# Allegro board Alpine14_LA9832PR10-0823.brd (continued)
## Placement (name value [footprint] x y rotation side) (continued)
CU16  0.1U_0402_10V7K~D  [C_0402]  93.62 53.65 0 bottom
CU17  0.1U_0402_10V7K~D  [C_0402]  93.62 54.54 0 bottom
CU18  0.1U_0402_10V7K~D  [C_0402]  93.62 51.81 0 bottom
CU19  0.1U_0402_10V7K~D  [C_0402]  93.62 52.7 0 bottom
CU20  0.1U_0402_10V7K~D  [C_0402]  97.81 55.99 0 bottom
CU21  0.1U_0402_10V7K~D  [C_0402]  97.81 56.87 0 bottom
CU22  0.1U_0402_10V7K~D  [C_0402]  95.59 54.92 0 bottom
CU23  0.1U_0402_10V7K~D  [C_0402]  95.59 55.81 0 bottom
CV86  10U_0603_6.3V6M  [C_0603]  51.79 74.86 180 top
CV87  0.1U_0402_10V7K~D  [C_0402]  76.38 77.48 180 top
CV88  1U_0402_6.3V6K  [C_0402]  63.34 78.87 270 top
CV89  1U_0402_6.3V6K  [C_0402]  59.99 78.86 180 top
CV90  10U_0603_6.3V6M  [C_0603]  64.3 79.24 0 top
CV91  10U_0603_6.3V6M  [C_0603]  56.74 76.53 0 top
CV94  1U_0402_6.3V6K  [C_0402]  57.45 78.99 180 top
CV95  1U_0402_6.3V6K  [C_0402]  54.38 77.27 0 top
CV96  10U_0603_6.3V6M  [C_0603]  59.53 76.83 0 top
CV97  1U_0402_6.3V6K  [C_0402]  60.93 78.87 270 top
CV100  1U_0402_6.3V6K  [C_0402]  56.16 82.6 0 top
CV101  1U_0402_6.3V6K  [C_0402]  56.57 87.49 180 top
CV102  10U_0603_6.3V6M  [C_0603]  50.64 88.19 0 top
CV103  1U_0402_6.3V6K  [C_0402]  63.1 89.84 180 top
CV104  15P_0402_50V8J  [C_0402]  66.83 98.54 0 bottom
CV105  15P_0402_50V8J  [C_0402]  65.9 98.54 180 bottom
CV226  0.1U_0402_10V7K~D  [C_0402]  68.05 78.3 270 top
CV227  0.1U_0402_10V7K~D  [C_0402]  62.33 78.87 270 top
CV228  0.1U_0402_10V7K~D  [C_0402]  56.16 84.19 0 top
CV231  0.1U_0402_10V7K~D  [C_0402]  57.74 89.84 0 top
CV232  0.1U_0402_10V7K~D  [C_0402]  51.67 94.1 180 top
CV233  0.1U_0402_10V7K~D  [C_0402]  65.31 89.28 270 top
CV234  0.1U_0402_10V7K~D  [C_0402]  66.46 89.28 270 top
CV235  0.1U_0402_10V7K~D  [C_0402]  63.98 89.28 270 top
CV236  0.1U_0402_10V7K~D  [C_0402]  68.36 87.35 90 top
CV239  0.1U_0402_10V7K~D  [C_0402]  68.36 85.03 270 top
CV240  0.1U_0402_10V7K~D  [C_0402]  69.25 85.45 90 top
CV2401  0.1U_0402_10V7K~D  [C_0402]  77.58 68.19 180 top
CV2402  0.1U_0402_10V7K~D  [C_0402]  75.74 72.57 180 top
CV2403  0.1U_0402_10V7K~D  [C_0402]  75.74 71.62 180 top
CV2404  0.1U_0402_10V7K~D  [C_0402]  73.65 71.24 180 top
CV2405  0.1U_0402_10V7K~D  [C_0402]  73.65 70.35 180 top
CV2406  0.1U_0402_10V7K~D  [C_0402]  70.92 69.46 180 top
CV2407  0.1U_0402_10V7K~D  [C_0402]  70.91 70.35 180 top
CV2408  0.1U_0402_10V7K~D  [C_0402]  77.58 67.3 180 top
CV2901  0.01U_0402_16V7K~D  [C_0402]  35.42 100.45 180 bottom
CV2902  0.01U_0402_16V7K~D  [C_0402]  33.55 97.78 0 top
CV2918  10U_0603_6.3V6M~D  [C_0603]  41.12 97.97 0 top
CV2919  10U_0603_6.3V6M~D  [C_0603]  41.25 97.97 180 bottom
CV2920  10U_0603_6.3V6M~D  [C_0603]  41.18 69.71 0 bottom
CV2921  10U_0603_6.3V6M~D  [C_0603]  26.77 80.06 90 top
CV2926  1U_0402_6.3V6K~D  [C_0402]  27.16 88.89 180 top
CV2927  1U_0402_6.3V6K~D  [C_0402]  38.21 98.73 180 top
CV2928  1U_0402_6.3V6K~D  [C_0402]  38.95 68.95 0 bottom
CV2929  1U_0402_6.3V6K~D  [C_0402]  30.72 85.65 180 top
CV2930  1U_0402_6.3V6K~D  [C_0402]  30.91 97.78 180 top
CV2931  1U_0402_6.3V6K~D  [C_0402]  40.15 85.72 0 top
CV2932  1U_0402_6.3V6K~D  [C_0402]  31.77 97.78 0 top
CV2933  1U_0402_6.3V6K~D  [C_0402]  40.18 97.78 180 top
CV2934  0.1U_0402_10V7K~D  [C_0402]  40.15 84.76 0 top
CV2935  0.1U_0402_10V7K~D  [C_0402]  38.21 97.78 180 top
CV2936  0.1U_0402_10V7K~D  [C_0402]  31.65 85.65 0 top
CV2937  0.1U_0402_10V7K~D  [C_0402]  38.91 85.59 180 top
CV2938  0.1U_0402_10V7K~D  [C_0402]  40.18 98.73 180 top
CV2939  0.1U_0402_10V7K~D  [C_0402]  38.91 84.64 180 top
CV2940  0.1U_0402_10V7K~D  [C_0402]  38.72 97.78 180 bottom
CV2941  0.01U_0402_16V7K~D  [C_0402]  35.33 97.78 0 top
CV2942  0.01U_0402_16V7K~D  [C_0402]  32.92 69.84 0 top
CV2943  0.01U_0402_16V7K~D  [C_0402]  35.14 82.22 0 top
CV2944  0.01U_0402_16V7K~D  [C_0402]  38.2 68.11 90 top
CV2945  0.1U_0402_10V7K~D  [C_0402]  30.02 97.78 180 bottom
CV2946  0.1U_0402_10V7K~D  [C_0402]  30.88 97.78 0 bottom
CV2947  0.1U_0402_10V7K~D  [C_0402]  30.02 98.67 180 bottom
CV2948  0.1U_0402_10V7K~D  [C_0402]  30.88 98.67 0 bottom
CV2949  0.1U_0402_10V7K~D  [C_0402]  30.91 98.67 180 top
CV2950  1U_0402_6.3V6K~D  [C_0402]  31.77 98.67 0 top
CV2951  1U_0402_6.3V6K~D  [C_0402]  32.03 68.89 0 bottom
CV2952  1U_0402_6.3V6K~D  [C_0402]  29.32 69.84 180 bottom
CV2953  0.1U_0402_10V7K~D  [C_0402]  37.32 68.95 180 bottom
CV2954  0.1U_0402_10V7K~D  [C_0402]  29.32 68.89 180 bottom
CV2955  0.1U_0402_10V7K~D  [C_0402]  32.03 69.84 0 bottom
CV2956  0.1U_0402_10V7K~D  [C_0402]  38.95 69.84 0 bottom
CV2957  0.1U_0402_10V7K~D  [C_0402]  37.32 69.84 180 bottom
CV2958  0.1U_0402_10V7K~D  [C_0402]  30.19 68.89 0 bottom
CV2959  1U_0402_6.3V6K~D  [C_0402]  30.19 69.84 0 bottom
CV2960  1U_0402_6.3V6K~D  [C_0402]  39.04 82.92 180 top
CV2961  1U_0402_6.3V6K~D  [C_0402]  29.32 68.89 180 top
CV2962  1U_0402_6.3V6K~D  [C_0402]  39.04 82.03 180 top
CV2963  0.1U_0402_10V7K~D  [C_0402]  40.15 81.97 0 top
CV2964  0.1U_0402_10V7K~D  [C_0402]  29.32 69.84 180 top
CV2965  0.1U_0402_10V7K~D  [C_0402]  40.15 83.81 0 top
CV2966  0.1U_0402_10V7K~D  [C_0402]  30.19 69.84 0 top
CV2967  0.1U_0402_10V7K~D  [C_0402]  31.98 69.85 270 top
CV2968  0.1U_0402_10V7K~D  [C_0402]  30.19 68.89 0 top
CV2969  1U_0402_6.3V6K~D  [C_0402]  40.15 82.86 0 top
CV3047  22U_0805_6.3V6M~D  [C_0805]  62.41 74.22 0 top
CV3048  4.7U_0603_6.3V6K~D  [C_0603]  61.95 76.83 0 top
CV3049  22U_0805_6.3V6M~D  [C_0805]  59.57 74.41 0 top
CV3050  22U_0805_6.3V6M~D  [C_0805]  56.65 74.41 0 top
CV3051  4.7U_0603_6.3V6K~D  [C_0603]  53.44 74.92 0 top
CV3052  22U_0805_6.3V6M~D  [C_0805]  53.29 73.4 0 top
CV3053  4.7U_0603_6.3V6K~D  [C_0603]  71.85 75.81 270 top
CV3054  4.7U_0603_6.3V6K~D  [C_0603]  67.66 79.94 0 top
CV3056  4.7U_0603_6.3V6K~D  [C_0603]  49 71.81 270 top
CV3057  22U_0805_6.3V6M~D  [C_0805]  75.03 88.23 90 top
CV3058  4.7U_0603_6.3V6K~D  [C_0603]  50.58 90.61 0 top
CV3059  22U_0805_6.3V6M~D  [C_0805]  49.37 86.5 270 top
CV3060  4.7U_0603_6.3V6K~D  [C_0603]  51.6 92.95 180 top
CV3061  4.7U_0603_6.3V6K~D  [C_0603]  63.22 90.8 90 top
CV3062  4.7U_0603_6.3V6K~D  [C_0603]  70.4 85.14 270 top
CV3063  22U_0805_6.3V6M~D  [C_0805]  71.92 85.3 270 top
CV3064  22U_0805_6.3V6M~D  [C_0805]  70.46 88.17 90 top
D1  RB751S40T1_SOD523-2~D  [RB751S40T1_SOD523-2]  74.84 97.78 270 top
D2  AZ5125-02S.R7G_SOT23-3  [AZ5125-02SPR7G_SOT23-3]  305.33 158.78 180 top
D12  RB751S40T1_SOD523-2~D  [RB751S40T1_SOD523-2]  275.67 159.94 0 bottom
D13  RB751S40T1_SOD523-2~D  [RB751S40T1_SOD523-2]  292.65 153.22 270 top
D14  RB751S40T1_SOD523-2~D  [RB751S40T1_SOD523-2]  298.81 157.6 180 top
D17  IP4292CZ10-TBR_XSON10_2.5X1~D  [IP4292CZ10-TBR_XSON10_2P5X1]  17.84 73.73 90 bottom
D18  PESD5V0U2BT_SOT23-3~D  [PESD5V0U2BT_SOT23-3]  17.47 76.06 270 top
D19  RB751S40T1_SOD523-2~D  [RB751S40T1_SOD523-2]  191.93 171.9 270 top
D20  PESD24VS2UT_SOT23-3~D  [PESD24VS2UT_SOT23-3]  134.53 171.91 0 bottom
D22  PESD5V0U2BT_SOT23-3~D  [PESD5V0U2BT_SOT23-3]  183.39 106.73 90 top
D23  RB751S40T1_SOD523-2~D  [RB751S40T1_SOD523-2]  174.22 4.25 270 top
D24  RB751S40T1_SOD523-2~D  [RB751S40T1_SOD523-2]  176.57 4.25 270 top
D27  -  [L30ESD24VC3-2_SOT23-3]  278.48 164.24 180 bottom
D65  RB751VM-40TE-17_SOD323-2~D  [RB751VM-40TE-17_SOD323-2]  21.58 102.65 0 top
D76  -  [BAT54CW_SOT323-3]  93.03 95.18 90 top
D77  PESD5V0U2BT_SOT23-3~D  [PESD5V0U2BT_SOT23-3]  102.23 137.28 90 top
D78  PESD5V0U2BT_SOT23-3~D  [PESD5V0U2BT_SOT23-3]  185.27 99.53 0 top
D79  -  [BAT54CW_SOT323-3]  108.46 117.4 90 top
D80  -  [BAT54CW_SOT323-3]  101.51 99.72 0 top
D87  PESD5V0U2BT_SOT23-3~D  [PESD5V0U2BT_SOT23-3]  195.96 170.74 90 top
D88  -  [L30ESDL5V0C3-2_SOT23-3]  78.21 94.39 0 top
DE1  -  [PESD5V0U2BT_SOT23-3]  199.52 126.67 90 top
DE2  -  [PESD5V0U2BT_SOT23-3]  199.52 122.67 90 top
FD1  FIDUCIAL MARK~D  [FIDUCIAL_C40M80]  5.24 10.41 180 bottom
FD2  FIDUCIAL MARK~D  [FIDUCIAL_C40M80]  294.61 174.43 0 top
FD3  FIDUCIAL MARK~D  [FIDUCIAL_C40M80]  5.24 10.41 0 top
FD4  FIDUCIAL MARK~D  [FIDUCIAL_C40M80]  296.14 174.03 180 bottom
H1  -  [H_4P6]  125.87 75.74 0 top
H2  -  [H_4P6]  105.87 9.74 0 top
H3  -  [H_4P3]  105.87 75.74 0 top
H4  -  [H_4P6]  125.87 9.74 0 top
H5  -  [H_2P8]  195.4 16.5 0 top
H6  -  [H_3P3]  309.6 146.6 0 top
H7  -  [H_2P8]  85.24 95.6 0 top
H8  -  [H_5P0]  8.9 4.6 0 top
H9  -  [H_2P8]  17.7 87.5 0 top
H10  -  [H_3P3X2P8]  195.4 53.5 0 top
H11  -  [H_2P8]  210.2 121.1 0 top
H12  -  [H_2P8]  309.6 173.6 0 top
H13  -  [H_2P8]  94.2 12.3 0 top
H14  -  [H_2P8]  207.5 171.5 90 top
H15  -  [H_2P8]  124.9 171.5 90 top
H16  -  [H_2P3]  85.4 151.85 90 top
H17  -  [H_1P2]  19.2 70 180 bottom
H18  -  [H_3P3]  8.94 16.97 0 top
H19  -  [H_3P3]  45.3 56.7 0 top
H20  -  [H_3P3]  78.64 112.21 0 top
H21  -  [H_3P3]  105.81 23.2 0 top
H22  -  [H_3P3]  80.81 19.3 0 top
H23  -  [H_3P3]  93.96 113.01 0 top
H24  -  [H_2P8]  80.57 120.59 0 top
HDMIU1  -  [AP2330W-7_SC59-3]  15.21 95.37 180 top
JAPS1  ACES_50506-01841-P01  [ACES_50506-01841-P01_18P]  152.19 67.24 0 top
JBIO1  ACES_51524-0060N-001  [ACES_51524-0060N-001_6P]  188.67 96.97 90 top
JBT1  ACES_50273-0020N-001  [ACES_50273-0020N-001_2P-T]  39.33 60.33 90 bottom
JDEG1  TYCO_1-2041070-0~D  [TYCO_1-2041070-0_10P]  151.1 121.76 270 top
JDIMM1  CONCR_0706F0BE80F  [CONCR_0706F0BE80F_204P]  175.7 8.35 90 bottom
JDIMM2  CONCR_0706E0BE40F  [CONCR_0706E0BE40F_204P]  162.57 8.35 90 bottom
JDOCK1  JAE_WD2F144WB3R300~D  [JAE_WD2F144WB3R300_144P]  147.45 164 0 bottom
JEXP1  E&T_1001K-F40C-03L  [E-T_1001K-F40C-03L_40P]  98.12 23.67 0 top
JFAN1  ACES_50281-0040N-001  [ACES_50281-0040N-001_4P]  69.82 99.53 270 top
JHDMI1  CONCR_099A6AC19CBLCNF  [CONCR_099A6AC19CBLCNF_19P]  10.93 90.3 90 bottom
JIO1  E-T_1000K-Y60E-01L  [E-T_1000K-Y60E-01L_60P-T]  306.52 167.46 270 bottom
JKB1  ACES_51524-01001-003  [ACES_51524-01001-003_10P]  189.51 110.23 180 top
JLED1  ACES_51522-01201-001  [ACES_51522-01201-001_12P]  184.95 4.85 90 top
JLVDS1  ACES_50398-04071-001  [ACES_50398-04071-001_40P]  95.9 140.42 90 top
JMED1  ACES_51522-00601-001  [ACES_51522-00601-001_6P]  177.31 155.75 270 top
JMINI1  LOTES_AAA-PCI-041-K01  [LOTES_AAA-PCI-041-K01_52P]  274.26 157.16 0 bottom
JMINI2  LOTES_AAA-PCI-041-K01  [LOTES_AAA-PCI-041-K01_52P]  211.31 129.1 90 bottom
JPWR1  ACES_51522-01001-001  [ACES_51522-01001-001_10P]  283.05 167.38 180 top
JSATA1  SANTA_196002-1  [SANTA_196002-1_22P]  85.2 107.33 270 bottom
JSATA2  SANTA_201902-1  [SANTA_201902-1_13P]  197.54 25.16 270 bottom
JSD1  ALPS_SCDADA0101_NR  [ALPS_SCDADA0101_19P_NR-T]  31.17 46.09 90 bottom
JSIM1  T-SOL_159-1000302602  [T-SOL_159-1000302602_10P]  230.09 159.22 0 bottom
JSPK1  ACES_50273-00401-001  [ACES_50273-00401-001_4P]  203.22 122.93 90 bottom
JTAA1  ACES_50051-02071-001  [ACES_50051-02071-001_20P-T]  22.98 23.68 270 bottom
JTAG1  @SHORT PADS~D  [SHORTPADS]  135.1 103.94 270 top
JTP1  ACES_51522-00801-001  [ACES_51522-00801-001_8P]  150.18 95.18 0 top
JTS1  E-T_4260K-Q06N-23L  [E-T_4260K-Q06N-23L_6P]  76.21 99.01 180 top
JUDB1  ACES_51522-02001-P02  [ACES_51522-02001-P02_20P]  90.4 87.55 270 top
JUSB1  SANTA_373280-4  [SANTA_373280-4_9P-T]  15.24 79.35 90 bottom
JXDP1  SAMTE_BSH-030-01-L-D-A  [SAMTE_BSH-030-01-L-D-A_60P]  148.65 12.24 180 top
L1  BLM18AG102SN1D_2P~D  [MURAT_BLM18AG102SN1D_2P]  109.26 99.47 90 top
L2  BLM18AG102SN1D_2P~D  [MURAT_BLM18AG102SN1D_2P]  128.62 112.23 90 top
L4  BLM18AG102SN1D_2P~D  [MURAT_BLM18AG102SN1D_2P]  109.17 98.1 0 top
L5  BLM18AG102SN1D_2P~D  [MURAT_BLM18AG102SN1D_2P]  112.59 111.05 0 top
L9  0_0402_5%~D  [R_0402]  17.09 97.72 180 bottom
L10  DLW21SN900HQ2L_0805_4P~D  [MURAT_DLW21SN900HQ2L_0805_4P]  17.49 97.8 180 bottom
L11  0_0402_5%~D  [R_0402]  17.09 98.73 180 bottom
L12  0_0402_5%~D  [R_0402]  17.09 100 180 bottom
L13  DLW21SN900HQ2L_0805_4P~D  [MURAT_DLW21SN900HQ2L_0805_4P]  17.49 100.09 180 bottom
L14  0_0402_5%~D  [R_0402]  17.09 101.02 180 bottom
L15  0_0402_5%~D  [R_0402]  17.09 95.5 180 bottom
L16  DLW21SN900HQ2L_0805_4P~D  [MURAT_DLW21SN900HQ2L_0805_4P]  17.49 95.58 180 bottom
L17  0_0402_5%~D  [R_0402]  17.09 96.51 180 bottom
L18  0_0402_5%~D  [R_0402]  17.09 92.89 180 bottom
L19  DLW21SN900HQ2L_0805_4P~D  [MURAT_DLW21SN900HQ2L_0805_4P]  17.49 92.97 180 bottom
L20  0_0402_5%~D  [R_0402]  17.09 93.91 180 bottom
L21  BLM21PG600SN1D_0805  [MURAT_BLM21PG600SN1D_2P]  266.81 147.66 270 bottom
L26  4.7UH_CBC2012T4R7M_20%~D  [TAIYO_CBC2012T4R7M_2P]  178.85 133.33 270 top
L27  0_0603_5%~D  [R0603_0OHM]  179.37 152.01 90 top
L28  0_0603_5%~D  [R0603_0OHM]  180.9 152.01 90 top
L29  0_0603_5%~D  [R0603_0OHM]  182.42 152.01 90 top
L30  0_0603_5%~D  [R0603_0OHM]  183.94 152.01 90 top
L31  0_0603_5%~D  [R0603_0OHM]  185.47 152.01 90 top
L32  0_0603_5%~D  [R0603_0OHM]  186.99 152.01 90 top
L33  0_0603_5%~D  [R0603_0OHM]  188.52 152.01 90 top
L34  0_0603_5%~D  [R0603_0OHM]  190.04 152.01 90 top
L35  BLM18BD601SN1D_0603~D  [MURAT_BLM18BD601SN1D_2P]  14.13 19.72 90 bottom
L36  BLM18BD601SN1D_0603~D  [MURAT_BLM18BD601SN1D_2P]  19.02 23.47 90 bottom
L37  0_0805_5%  [R0805_0OHM]  243.62 149.61 90 bottom
L40  DLW21SN900HQ2L_0805_4P~D  [MURAT_DLW21SN900HQ2L_0805_4P]  22.48 73.29 180 bottom
L41  DLW21SN900HQ2L_0805_4P~D  [MURAT_DLW21SN900HQ2L_0805_4P]  22.22 75.07 180 bottom
L42  DLW21SN900SQ2L_0805_4P~D  [MURAT_DLW21SN900SQ2L_0805_4P]  23.22 76.46 180 top
L43  DLW21SN900SQ2L_0805_4P~D  [MURAT_DLW21SN900SQ2L_0805_4P]  164.8 166.97 90 top
L44  0_0603_5%~D  [R0603_0OHM]  181.08 103.05 0 top
L45  0_0603_5%~D  [R0603_0OHM]  180 103.05 180 top
L46  DLW21SN900SQ2L_0805_4P~D  [MURAT_DLW21SN900SQ2L_0805_4P]  19.81 34.57 90 bottom
L47  DLW21SN900SQ2L_0805_4P~D  [MURAT_DLW21SN900SQ2L_0805_4P]  17.58 34.57 90 bottom
L48  DLW21SN900SQ2L_0805_4P~D  [MURAT_DLW21SN900SQ2L_0805_4P]  15.3 34.57 90 bottom
L49  BLM18PG471SN1D_2P~D  [MURAT_BLM18PG471SN1D_2P]  96.02 107.37 0 top
L50  BLM18PG471SN1D_2P~D  [MURAT_BLM18PG471SN1D_2P]  100.37 103.79 90 top
L51  BLM18PG471SN1D_2P~D  [MURAT_BLM18PG471SN1D_2P]  108.78 112.64 0 top
L52  DLW21SN900SQ2L_0805_4P~D  [MURAT_DLW21SN900SQ2L_0805_4P]  101.41 134.78 180 top
L53  DLW21SN900SQ2L_0805_4P~D  [MURAT_DLW21SN900SQ2L_0805_4P]  166.77 166.97 90 top
L54  OCF2012181YZF_4P  [SWLD_OCF2012181YZF_4P]  187.52 106.39 225 top
L55  DLW21SN900HQ2L_0805_4P~D  [MURAT_DLW21SN900HQ2L_0805_4P]  168.74 166.97 90 top
L56  DLW21SN900HQ2L_0805_4P~D  [MURAT_DLW21SN900HQ2L_0805_4P]  170.71 166.97 90 top
L57  DLW21SN900SQ2L_0805_4P~D  [MURAT_DLW21SN900SQ2L_0805_4P]  223.85 146.41 180 bottom
L58  DLW21SN900SQ2L_0805_4P~D  [MURAT_DLW21SN900SQ2L_0805_4P]  80.47 91.03 90 top
L59  DLW21SN900SQ2L_0805_4P~D  [MURAT_DLW21SN900SQ2L_0805_4P]  96.28 20.59 270 bottom
L69  0_0402_5%  [R0402_0OHM]  162.47 159.68 90 bottom
L70  0_0402_5%  [R0402_0OHM]  161.45 159.68 90 bottom
L71  0_0402_5%  [R0402_0OHM]  160.44 159.68 90 bottom
L72  DLW21SN900SQ2L_0805_4P~D  [MURAT_DLW21SN900SQ2L_0805_4P]  166.95 115.07 0 top
L73  BLM18PG300SN1D_2P~D  [MURAT_BLM18PG300SN1D_2P]  73.47 87.75 180 top
LC1  2.2UH +-20% LQM21PN2R2MC0D  [MURAT_LQM2MPN2R2NG0L_2P]  94.7 57.9 0 bottom
LC2  2.2UH +-20% LQM21PN2R2MC0D  [MURAT_LQM2MPN2R2NG0L_2P]  93.92 63.05 0 bottom
LC3  2.2UH_LQM2MPN2R2NG0L_30%  [MURAT_LQM2MPN2R2NG0L_2P]  95.31 58.22 0 top
LC4  2.2UH_LQM2MPN2R2NG0L_30%  [MURAT_LQM2MPN2R2NG0L_2P]  97.29 64.51 180 top
LC5  2.2UH_LQM2MPN2R2NG0L_30%  [MURAT_LQM2MPN2R2NG0L_2P]  92.87 55.08 270 top
LC6  2.2UH_LQM2MPN2R2NG0L_30%  [MURAT_LQM2MPN2R2NG0L_2P]  94.8 55.93 0 top
LE2  0_0603_5%~D  [R0603_0OHM]  100.71 132.71 180 top
LE3  0_0603_5%~D  [R0603_0OHM]  246.45 158.8 180 bottom
LE4  0_0603_5%~D  [R0603_0OHM]  247.47 158.8 0 bottom
LV74  BLM18AG121SN1D_2P  [MURAT_BLM18AG121SN1D_2P]  50.17 71.56 0 top
LV76  BLM18PG300SN1D_2P~D  [MURAT_BLM18PG300SN1D_2P]  75.03 87.08 270 top
LV80  BLM18PG181SN1D_2P  [MURAT_BLM18PG181SN1D_2P]  73.57 84.04 90 top
ME1  SHORT PADS~D  [SHORTPADS]  147.23 71.94 0 bottom
NOREF  -  []  8.94 16.97 0 top
NOREF#2  -  []  94.2 12.3 180 top
NOREF#3  -  []  210.2 121.1 180 top
NOREF#4  -  []  19.2 70 90 top
NOREF#5  -  []  20.42 14.15 0 top
NOREF#6  -  []  207.5 171.5 0 top
NOREF#7  -  []  -4.17 -32.65 0 top
NOREF#8  -  []  79.89 202.62 0 top
NOREF#9  -  []  105.81 23.2 0 top
NOREF#10  -  []  309.6 146.6 180 top
NOREF#11  -  []  80.57 120.59 45 top
NOREF#12  -  []  80.81 19.3 0 top
NOREF#13  -  []  85.24 95.6 0 top
NOREF#14  -  []  195.4 16.5 270 top
NOREF#15  -  []  93.96 113.01 0 top
NOREF#16  -  []  309.6 173.6 0 top
NOREF#17  -  []  17.7 87.5 0 top
NOREF#18  -  []  91.41 -29.22 0 top
NOREF#19  -  []  78.64 112.21 0 top
NOREF#20  -  []  45.3 56.7 0 top
NOREF#21  -  []  124.9 171.5 0 top
NOREF#22  -  []  -22.35 -13.74 0 top
NOREF#23  -  []  107.67 -34.65 0 top
NOREF#24  -  []  195.4 53.5 270 top
NOREF#25  -  []  201.71 -75.46 0 top
NOREF#26  -  []  8.9 4.6 180 top
NOREF#27  -  []  85.4 151.85 0 top
NOREF#28  -  []  -13.31 -35.29 90 bottom
NOREF#29  -  []  182.73 -9.8 180 bottom
PBATT2  ACES_51996-00971-001  [ACES_51996-00971-001_9P]  88.46 173 0 bottom
PC3  2200P_0402_50V7K  [C_0402]  102.03 169.09 180 top
PC4  1500P_0402_50V7K  [C_0402]  127.23 120.97 270 top
PC5  0.022U_0603_50V7K  [C_0603]  120.02 129.28 0 top
PC6  0.1U_0603_25V7K  [C_0603]  95.41 147.31 270 top
PC9  10U_0805_25V6K  [C_0805]  91.35 147.72 270 top
PC10  0.1U_0603_25V7K  [C_0603]  87.55 156.87 270 top
PC11  0.1U_0603_25V7K  [C_0603]  92.62 159 90 bottom
PC12  0.1U_0603_25V7K  [C_0603]  82.9 167.57 180 bottom
PC51  1U_0603_10V6K  [C_0603]  186.92 138.36 90 top
PC52  10U_0805_25V6K  [C_0805]  197.27 142.19 270 top
PC53  0.1U_0402_25V6  [C_0402]  199.55 140.34 270 top
PC54  2200P_0402_50V7K  [C_0402]  198.66 140.34 270 top
PC55  0.1U_0402_25V6  [C_0402]  198.6 144.12 90 top
PC56  10U_0805_25V6K  [C_0805]  195.49 142.19 270 top
PC57  2200P_0402_50V7K  [C_0402]  199.49 144.12 90 top
PC58  10U_0805_25V6K  [C_0805]  195.49 143.41 90 top
PC59  10U_0805_25V6K  [C_0805]  197.27 143.41 90 top
PC60  0.1U_0603_25V7K  [C_0603]  190.41 148.2 270 top
PC61  0.1U_0603_25V7K  [C_0603]  190.15 139.25 270 top
PC62  680P_0603_50V7K  [C_0603]  202.28 134.19 180 top
PC65  680P_0603_50V7K  [C_0603]  202.03 150.23 180 top
PC67  0.1U_0603_25V7K  [C_0603]  193.9 145.66 90 top
PC68  0.1U_0603_25V7K  [C_0603]  193.97 140.71 270 top
PC69  1U_0603_10V6K  [C_0603]  193.97 143.25 270 top
PC70  1U_0603_10V6K  [C_0603]  188.25 146.99 180 top
PC71  220U_D2_6.3VY_R15M  [C_D2]  202.44 130.99 0 top
PC72  220U_D2_6.3VY_R15M  [C_D2]  206.27 149.53 90 bottom
PC100  10U_0805_25V6K  [C_0805]  189.94 79.05 0 top
PC101  10U_0805_25V6K  [C_0805]  189.94 77.14 0 top
PC102  0.1U_0402_25V6  [C_0402]  191.22 75.17 0 bottom
PC103  2200P_0402_50V7K  [C_0402]  194.35 80.46 270 bottom
PC104  0.22U_0603_16V7K  [C_0603]  179.42 77.97 180 top
PC105  10U_0805_6.3V6M  [C_0805]  178.6 85.44 90 top
PC106  10U_0805_6.3V6M  [C_0805]  176.82 85.44 90 top
PC107  1U_0603_10V6K  [C_0603]  176.35 76.71 90 top
PC109  680P_0603_50V7K  [C_0603]  184.12 78.03 90 top
PC110  330U_2.5V_M  [C_MP2VLPS330MC4R2]  189.65 49.15 90 bottom
PC111  1U_0603_10V6K  [C_0603]  172.76 77.97 180 top
PC112  0.033U_0402_16V7K  [C_0402]  175.42 85.45 90 top
PC113  100P_0402_50V8J  [C_0402]  173.64 86.36 270 top
PC114  0.1U_0402_10V7K  [C_0402]  172.76 85.45 90 top
PC115  0.1U_0402_10V7K  [C_0402]  171.56 81.97 180 top
PC116  330U_D2_2.5VY_R15M  [C_D2]  188.35 63.94 0 top
PC150  4700P_0402_25V7K  [C_0402]  153.31 77.46 0 top
PC151  1U_0402_6.3V6K  [C_0402]  153.33 78.34 90 top
PC152  0.1U_0402_25V6  [C_0402]  155.43 80.56 90 bottom
PC153  2200P_0402_50V7K  [C_0402]  156.32 80.56 90 bottom
PC154  10U_0805_25V6K  [C_0805]  159.42 79.53 90 bottom
PC155  10U_0805_25V6K  [C_0805]  157.64 79.53 90 bottom
PC156  0.1U_0402_10V7K  [C_0402]  154.02 73.83 90 top
PC157  0.1U_0402_10V7K  [C_0402]  151.36 74.87 270 top
PC158  22U_0805_6.3VAM  [C_0805]  143.06 77.42 180 top
PC159  22U_0805_6.3VAM  [C_0805]  143.06 75.71 180 top
PC163  22U_0805_6.3VAM  [C_0805]  143.06 79.14 180 top
PC164  680P_0603_50V7K  [C_0603]  146.91 79.3 0 top
PC165  0.1U_0603_25V7K  [C_0603]  150.72 79.24 90 top
PC200  22U_0805_6.3VAM  [C_0805]  265.15 165.89 90 bottom
PC201  0.1U_0603_25V7K  [C_0603]  263.62 165.92 90 bottom
PC202  22P_0402_50V8J  [C_0402]  270.05 163.57 180 bottom
PC203  22U_0805_6.3VAM  [C_0805]  265.15 170.64 270 bottom
PC204  22U_0805_6.3VAM  [C_0805]  263.37 170.64 270 bottom
PC205  47P_0402_50V8J  [C_0402]  261.97 170.5 270 bottom
PC206  0.1U_0402_10V7K  [C_0402]  271.17 164.71 0 bottom
PC207  680P_0603_50V7K  [C_0603]  274.36 168.96 90 bottom
PC300  4700P_0603_50V7K  [C_0603]  49.5 12.95 0 bottom
PC301  0.1U_0402_10V7K  [C_0402]  47.66 13.72 270 bottom
PC302  0.1U_0402_25V7K  [C_0402]  66.53 21.84 180 bottom
PC303  2.2U_0603_10V7K  [C_0603]  69.75 27.87 90 bottom
PC304  0.1U_0402_25V7K  [C_0402]  65.43 27.87 0 bottom
PC305  100P_0402_50V8J  [C_0402]  46.83 20.49 90 bottom
PC306  1U_0603_10V6K  [C_0603]  55.09 21.77 0 bottom
PC307  680P_0603_50V7K  [C_0603]  69.38 19.87 0 bottom
PC308  1500P_0402_50V7K  [C_0402]  45.06 20.49 90 bottom
PC309  0.33U_0603_10V7K  [C_0603]  47.09 22.53 90 bottom
PC310  1U_0603_10V6K  [C_0603]  49.63 22.53 90 bottom
PC311  10U_0805_25VAK  [C_0805]  65.42 20.44 0 bottom
PC312  10U_0805_25VAK  [C_0805]  63.15 23.51 270 bottom
PC313  10U_0805_25VAK  [C_0805]  61.38 23.51 270 bottom
PC314  10U_0805_25VAK  [C_0805]  59.6 23.51 270 bottom
PC315  33U_D_25VM_R60M  [C_D]  61.31 18.66 270 bottom
PC316  33U_D_25VM_R60M  [C_D]  66.96 14.53 0 bottom
PC317  47P_0402_50V8J  [C_0402]  51.09 23.75 270 bottom
PC318  0.068U_0402_16V7K  [C_0402]  46.71 15.85 90 bottom
PC319  0.1U_0402_10V7K  [C_0402]  54.65 23.75 270 bottom
PC320  0.068U_0402_16V7K  [C_0402]  45.82 15.85 90 bottom
PC321  1000P_0402_50V7K  [C_0402]  78.27 55.87 180 bottom
PC322  0.1U_0402_25V6  [C_0402]  78.27 56.76 180 bottom
PC323  0.1U_0402_25V6  [C_0402]  63.55 43.74 180 bottom
PC324  1000P_0402_50V7K  [C_0402]  63.55 44.63 180 bottom
PC360  22U_0805_6.3VAM  [C_0805]  95.09 32.03 90 bottom
PC361  22U_0805_6.3VAM  [C_0805]  95.09 37.54 270 bottom
PC362  22U_0805_6.3VAM  [C_0805]  83.66 29.92 270 bottom
PC363  22U_0805_6.3VAM  [C_0805]  85.95 29.92 270 bottom
PC364  22U_0805_6.3VAM  [C_0805]  90.52 29.92 270 bottom
PC365  22U_0805_6.3VAM  [C_0805]  83.66 32.03 90 bottom
PC366  22U_0805_6.3VAM  [C_0805]  83.66 37.54 270 bottom
PC367  22U_0805_6.3VAM  [C_0805]  95.09 29.92 270 bottom
PC368  22U_0805_6.3VAM  [C_0805]  88.24 29.92 270 bottom
PC369  22U_0805_6.3VAM  [C_0805]  92.81 29.92 270 bottom
PC370  22U_0805_6.3VAM  [C_0805]  88.24 47.27 90 bottom
PC371  22U_0805_6.3VAM  [C_0805]  85.95 45.16 270 bottom
PC372  22U_0805_6.3VAM  [C_0805]  90.52 32.03 90 bottom
PC373  22U_0805_6.3VAM  [C_0805]  90.52 37.54 270 bottom
PC374  22U_0805_6.3VAM  [C_0805]  92.81 32.03 90 bottom
PC375  22U_0805_6.3VAM  [C_0805]  92.81 37.54 270 bottom
PC376  22U_0805_6.3VAM  [C_0805]  90.52 39.65 90 bottom
PC377  22U_0805_6.3VAM  [C_0805]  92.81 39.65 90 bottom
PC378  22U_0805_6.3VAM  [C_0805]  90.52 45.16 270 bottom
PC379  22U_0805_6.3VAM  [C_0805]  92.81 45.16 270 bottom
PC380  22U_0805_6.3VAM  [C_0805]  90.52 47.27 90 bottom
PC381  22U_0805_6.3VAM  [C_0805]  92.81 47.27 90 bottom
PC382  22U_0805_6.3VAM  [C_0805]  88.24 45.16 270 bottom
PC383  22U_0805_6.3VAM  [C_0805]  88.24 39.65 90 bottom
PC384  22U_0805_6.3VAM  [C_0805]  85.95 32.03 90 bottom
PC385  22U_0805_6.3VAM  [C_0805]  88.24 32.03 90 bottom
PC386  22U_0805_6.3VAM  [C_0805]  85.95 47.27 90 bottom
PC387  22U_0805_6.3VAM  [C_0805]  85.95 37.54 270 bottom
PC388  22U_0805_6.3VAM  [C_0805]  88.24 37.54 270 bottom
PC389  22U_0805_6.3VAM  [C_0805]  85.95 39.65 90 bottom
PC400  0.1U_0603_25V7K  [C_0603]  100.43 151.76 270 top
PC401  47P_0402_50V8J  [C_0402]  98.53 165.78 90 top
PC402  0.1U_0603_25V7K  [C_0603]  100.05 165.54 90 top
PC406  0.1U_0603_25V7K  [C_0603]  117.38 132.26 270 top
PC407  0.1U_0402_25V6  [C_0402]  111.42 140.69 90 top
PC408  0.1U_0402_25V6  [C_0402]  110.53 141.6 180 top
PC409  0.1U_0402_25V6  [C_0402]  108.69 141.61 270 top
PC410  1U_0603_10V6K  [C_0603]  107.35 147.95 180 top
PC411  10U_0805_25V6K  [C_0805]  106.4 140.11 90 top
PC412  0.1U_0603_25V7K  [C_0603]  97.64 165.23 90 bottom
PC413  0.1U_0402_25V6  [C_0402]  115.49 142.74 180 top
PC414  2200P_0402_50V7K  [C_0402]  97.57 165.78 90 top
PC415  22U_0805_25V6M  [C_0805]  100.37 162.45 270 top
PC416  22U_0805_25V6M  [C_0805]  98.59 162.45 270 top
PC417  0.047U_0603_25V7M  [C_0603]  105.32 145.28 0 top
PC418  1000P_0603_50V7K  [C_0603]  104.69 161.22 180 top
PC419  10U_0805_25V6K  [C_0805]  119.9 165.66 0 top
PC420  10U_0805_25V6K  [C_0805]  119.9 163.88 0 top
PC421  0.1U_0603_25V7K  [C_0603]  116.88 153.66 180 top
PC422  10U_0805_25V6K  [C_0805]  117.03 155.18 180 top
PC423  10U_0805_25V6K  [C_0805]  117.03 156.96 180 top
PC424  100P_0402_50V8J  [C_0402]  114.58 144.52 0 top
PC425  0.1U_0402_25V6  [C_0402]  109.63 149.03 0 top
PC426  0.1U_0402_25V6  [C_0402]  110.51 149.91 0 top
PC427  0.1U_0402_25V6  [C_0402]  111.47 149.03 0 top
PC428  100P_0402_50V8J  [C_0402]  109.32 119.96 270 top
PC429  0.01UF_0402_25V7K  [C_0402]  108.43 119.96 270 top
PC430  22U_0805_25V6M  [C_0805]  97.13 162.39 270 bottom
PC431  100P_0402_50V8J  [C_0402]  114.01 122.61 0 top
PC432  220P_0402_25V8J  [C_0402]  113.99 124.01 0 top
PC433  0.1U_0402_10V7K  [C_0402]  122.67 116.64 180 top
PC434  100P_0402_50V8J  [C_0402]  105.33 125.72 180 top
PC435  100P_0402_50V8J  [C_0402]  105.33 123.05 180 top
PC436  22U_0805_25V6M  [C_0805]  96.11 165.26 90 bottom
PC437  22U_0805_25V6M  [C_0805]  98.91 162.39 270 bottom
PC438  1U_0603_25V6  [C_0603]  112.5 140.2 90 top
PC439  1200P_0402_50V7K  [C_0402]  115.16 118.66 90 top
PC440  0.1U_0402_25V6  [C_0402]  119.67 167.93 0 top
PC441  2200P_0402_50V7K  [C_0402]  119.67 167 0 top
PC500  0.1U_0402_10V7K  [C_0402]  138.33 132.71 0 top
PC502  0.1U_0402_10V7K  [C_0402]  141.63 128.77 0 top
PC503  0.1U_0603_25V7K  [C_0603]  141.83 159.95 270 top
PC504  2200P_0402_50V7K  [C_0402]  142.97 159.96 270 top
PC505  0.47U_0805_25V6K  [C_0805]  141.87 161.41 0 top
PC506  0.01U_0603_25V7K  [C_0603]  137.07 147.76 270 top
PC507  0.1U_0402_10V7K  [C_0402]  143.8 151.45 270 top
PC508  0.1U_0402_10V7K  [C_0402]  144.37 154.5 270 top
PC509  1500P_0402_50V7K  [C_0402]  129.84 166.36 180 top
PC510  0.1U_0402_10V7K  [C_0402]  142.01 155.69 0 top
PC511  0.1U_0603_50V4Z  [C_0603]  120.62 133.53 270 top
PC512  0.1U_0603_25V7K  [C_0603]  121.71 133.42 0 top
PC513  0.047U_0603_25V7M  [C_0603]  127.99 136.58 0 top
PC514  0.1U_0402_25V6  [C_0402]  128.23 137.72 0 top
PC515  0.1U_0402_10V7K  [C_0402]  145.71 132.16 0 top
PC600  10U_0805_25VAK  [C_0805]  78.92 54.54 180 bottom
PC601  10U_0805_25VAK  [C_0805]  81.93 56.25 0 bottom
PC602  10U_0805_25V6K  [C_0805]  81.93 54.54 0 bottom
PC603  10U_0805_25V6K  [C_0805]  63.94 45.97 180 bottom
PC604  10U_0805_25VAK  [C_0805]  63.94 47.68 180 bottom
PC605  10U_0805_25VAK  [C_0805]  63.94 49.39 180 bottom
PC612  0.1U_0603_25V7K  [C_0603]  58.77 41.14 270 bottom
PC613  1U_0402_6.3V6K  [C_0402]  55.6 30.42 270 bottom
PC614  47P_0402_50V8J  [C_0402]  61.11 36.06 0 bottom
PC615  680P_0603_50V7K  [C_0603]  80.05 43.62 270 bottom
PC616  1800P_0402_50V7K  [C_0402]  58.28 27.68 180 bottom
PC617  1800P_0402_50V7K  [C_0402]  57.38 29.53 270 bottom
PC619  0.01UF_0402_25V7K  [C_0402]  54.7 28.57 0 bottom
PC620  33P_0402_50V8J  [C_0402]  52.04 29 90 bottom
PC621  0.1U_0402_10V7K  [C_0402]  56.81 41.22 270 bottom
PC622  470P_0402_50V7K  [C_0402]  51.15 30.84 90 bottom
PC623  47P_0402_50V8J  [C_0402]  52.04 30.84 90 bottom
PC624  0.01U_0402_16V7K  [C_0402]  52.04 33.53 270 bottom
PC625  0.01U_0402_16V7K  [C_0402]  52.12 37.27 180 bottom
PC626  0.01U_0402_16V7K  [C_0402]  52.12 36.38 180 bottom
PC627  0.1U_0603_25V7K  [C_0603]  54.46 41.27 270 bottom
PC628  680P_0603_50V7K  [C_0603]  49.25 44.95 270 bottom
PC660  4.7U_0603_6.3VAK  [C_0603]  61.44 80.89 90 top
PC661  4.7U_0603_6.3VAK  [C_0603]  58.29 85.81 180 top
PC662  4.7U_0603_6.3VAK  [C_0603]  57.44 80.76 180 top
PC663  4.7U_0603_6.3VAK  [C_0603]  61.51 85.27 270 top
PC664  4.7U_0603_6.3VAK  [C_0603]  63.47 85.65 270 top
PC665  4.7U_0603_6.3VAK  [C_0603]  60.62 88.64 90 top
PC666  4.7U_0603_6.3VAK  [C_0603]  63.28 80.95 90 top
PC667  4.7U_0603_6.3VAK  [C_0603]  59.16 88.13 180 top
PC668  4.7U_0603_6.3VAK  [C_0603]  65 84.19 0 top
PC669  4.7U_0603_6.3VAK  [C_0603]  64.68 85.91 0 top
PC670  0.1U_0402_10V7K  [C_0402]  59.22 84.84 270 top
PC671  0.1U_0402_10V7K  [C_0402]  62.13 87.62 0 top
PC672  0.1U_0402_10V7K  [C_0402]  65.05 81.4 0 top
PC673  0.1U_0402_10V7K  [C_0402]  59.42 82.22 180 top
PC674  47U_0805_6.3V6M  [C_0805]  49.44 61.04 270 bottom
PC675  22U_0805_6.3VAM  [C_0805]  51.22 61.04 270 bottom
PC676  4.7U_0603_6.3VAK  [C_0603]  52.74 60.89 270 bottom
PC677  4.7U_0603_6.3VAK  [C_0603]  46.84 62.54 180 bottom
PC678  4.7U_0603_6.3VAK  [C_0603]  46.84 61.33 180 bottom
PC679  4.7U_0603_6.3VAK  [C_0603]  46.84 63.75 180 bottom
PC680  4.7U_0603_6.3VAK  [C_0603]  62.33 58.6 270 bottom
PC683  330U_X_2VM_R6M  [C_X]  65.44 64.07 270 bottom
PC684  330U_X_2VM_R6M  [C_X]  69.39 63.1 0 bottom
PC700  0.1U_0402_25V6  [C_0402]  43.23 33.33 180 bottom
PC701  2200P_0402_50V7K  [C_0402]  43.23 32.44 180 bottom
PC702  10U_0805_25V6K  [C_0805]  44.19 30.47 180 bottom
PC703  10U_0805_25V6K  [C_0805]  45.35 30.47 0 bottom
PC704  0.1U_0603_25V7K  [C_0603]  39.6 28.38 90 bottom
PC705  680P_0603_50V7K  [C_0603]  47.34 37.52 270 bottom
PC706  1U_0402_6.3V6K  [C_0402]  37.89 33.26 180 bottom
PC708  0.1U_0402_10V7K  [C_0402]  32.81 31.99 180 bottom
PC709  330U_2.5V_M  [C_APXK2R5ARA331MF451]  37.63 46.67 90 bottom
PD1  -  [TVNST52302AB0_SOT523-3]  96.18 169.47 270 top
PD2  -  [TVNST52302AB0_SOT523-3]  97.14 169.49 90 top
PD4  -  [RB751VM-40TE-17_SOD323-2]  126.4 129.52 270 top
PD5  -  [BAV99W-7-F_SOT323-3]  122.22 122.81 0 top
PD300  -  [SDMK0340L-7-F_SOD323-2]  57.87 22.48 270 bottom
PD400  -  [BAT54CW_SOT323-3]  101.45 146.77 180 top
PD401  -  [BAT54HT1G_SOD323-2]  104.37 146.84 90 top
PD500  -  [PDS5100H-13_POWERDI5-3]  128.56 156.07 0 top
PD501  -  [SDMK0340L-7-F_SOD323-2]  133.14 145.53 0 top
PD502  -  [PDS5100H-13_POWERDI5-3]  120.94 160.65 0 top
PD503  -  [SDMK0340L-7-F_SOD323-2]  121.06 151.88 0 top
PD504  -  [SDMK0340L-7-F_SOD323-2]  143.74 133.54 90 top
PD505  -  [PDS5100H-13_POWERDI5-3]  138.59 156.2 180 top
PD506  -  [SDMK0340L-7-F_SOD323-2]  146.15 158.8 270 top
PD507  -  [SDMK0340L-7-F_SOD323-2]  132.05 137.21 270 top
PD508  -  [SDMK0340L-7-F_SOD323-2]  144.37 158.8 270 top
PD509  -  [SDMK0340L-7-F_SOD323-2]  119.76 146.1 180 top
PD510  -  [SDMK0340L-7-F_SOD323-2]  133.83 137.21 270 top
PD511  -  [SDMK0340L-7-F_SOD323-2]  121.89 146.73 270 top
PD512  -  [SDMK0340L-7-F_SOD323-2]  137.46 171.27 0 top
PD513  -  [SDMK0340L-7-F_SOD323-2]  145.76 134.27 0 top
PD514  -  [SDMK0340L-7-F_SOD323-2]  114.16 152.2 180 top
PD601  -  [SDMK0340L-7-F_SOD323-2]  62.52 39.86 270 bottom
PH300  100K_0402_1%_NCP15WF104F03RC  [R_0402]  67.51 28.08 0 bottom
PH301  10K_0402_1%_TSM0A103F34D1RZ  [R_0402]  69.75 33.2 0 bottom
PH302  10K_0402_1%_TSM0A103F34D1RZ  [R_0402]  49.76 50.21 90 bottom
PJP2  PAD-OPEN1x1m  [JUMP_43X39]  161.2 121.01 90 top
PJP3  PAD-OPEN1x1m  [JUMP_43X39]  83.22 114.91 90 top
PJP4  PAD-OPEN1x1m  [JUMP_43X39]  301.1 151.57 180 top
PJP5  PAD-OPEN1x1m  [JUMP_43X39]  160.25 118.56 270 top
PJP6  PAD-OPEN1x1m  [JUMP_43X39]  160.31 88.69 90 top
PJP7  PAD-OPEN1x1m  [JUMP_43X39]  148.5 118.49 270 top
PJP8  PAD-OPEN1x1m  [JUMP_43X39]  146.53 87.67 90 top
PJP9  PAD-OPEN1x1m  [JUMP_43X39]  87.79 114.02 90 top
PJP10  PAD-OPEN1x1m  [JUMP_43X39]  98.7 140.9 0 top
PJP11  PAD-OPEN1x1m  [JUMP_43X39]  117.63 52.82 0 top
PJP12  PAD-OPEN1x1m  [JUMP_43X39]  179.12 125.91 180 top
PJP13  PAD-OPEN1x1m  [JUMP_43X39]  72.49 105.02 90 top
PJP52  PAD-OPEN 1x3m  [JUMP_43X118]  206.98 153.43 90 top
PJP53  PAD-OPEN 1x3m  [JUMP_43X118]  199.09 131.25 180 top
PJP101  PAD-OPEN1x1m  [JUMP_43X39]  178.52 83.24 0 top
PJP102  JUMP_1x3m  [JUMP_43X118]  188.36 58.92 180 top
PJP103  JUMP_1x3m  [JUMP_43X118]  188.36 55.93 180 bottom
PJP104  PAD-OPEN1x1m  [JUMP_43X39]  180.63 85.51 90 top
PJP150  PAD-OPEN 1x2m~D  [JUMP_43X79]  162.5 77.94 180 bottom
PJP151  PAD-OPEN 1x3m  [JUMP_43X118]  138.51 78.35 180 top
PJP152  PAD-OPEN 1x2m~D  [JUMP_43X79]  81.06 80.98 90 bottom
PJP200  PAD-OPEN 1x2m~D  [JUMP_43X79]  259.27 167.44 0 bottom
PJP201  PAD-OPEN 1x2m~D  [JUMP_43X79]  260.37 171.38 180 bottom
PJP401  PAD-OPEN1x1m  [JUMP_43X39]  113.5 149.98 0 top
PJP600  -  [JUMP_43X118]  66.08 38.43 90 bottom
PJP601  PAD-OPEN 1x3m  [JUMP_43X118]  55.16 64.4 90 bottom
PJP602  PAD-OPEN 1x3m  [JUMP_43X118]  60.36 64.4 90 bottom
PJP603  PAD-OPEN 1x3m  [JUMP_43X118]  49.95 64.4 90 bottom
PJP700  PAD-OPEN 1x2m~D  [JUMP_43X79]  44.74 26.75 90 bottom
PJP701  PAD-OPEN 1x2m~D  [JUMP_43X79]  41.69 50.94 90 bottom
PJP702  PAD-OPEN 1x2m~D  [JUMP_43X79]  37.88 50.94 90 bottom
PJP802  PAD-OPEN1x1m  [JUMP_43X39]  191.72 39.74 180 bottom
PJPDC1  ACES_50299-00501-003  [ACES_50299-00501-003_5P]  83.72 157.8 42.2 top
PL1  FBMJ4516HS720NT_2P  [TAIYO_FBMJ4516HS720NT_2P]  110.39 170.93 0 top
PL2  FBMJ4516HS720NT_2P  [TAIYO_FBMJ4516HS720NT_2P]  110.39 168.65 0 top
PL3  BLM18BD102SN1D_2P  [MURAT_BLM18BD102SN1D_2P]  114.69 129.28 0 top
PL4  FBMA-L11-453215800LMA90T_2P  [KC_FBMA-L11-453215800LMA90T_2P]  89.26 157.95 0 top
PL5  FBMA-L11-453215800LMA90T_2P  [KC_FBMA-L11-453215800LMA90T_2P]  84.11 164.9 180 bottom
PL51  1UH_PCMB053T-1R0MS_7A_20%  [CYNTE_PCMB053T-1R0MS_2P]  200.13 153.93 270 bottom
PL52  2.2UH_ETQP3W2R2WFN_8.5A_20%  [PANAS_ETQP3W2R2WFN_2P]  206.54 136.45 0 bottom
PL53  2.2UH_ETQP3W2R2WFN_8.5A_20%  [PANAS_ETQP3W2R2WFN_2P]  200.69 143.63 180 bottom
PL100  2.2UH_ETQP3W2R2WFN_8.5A_20%  [PANAS_ETQP3W2R2WFN_2P]  189.46 63.42 270 bottom
PL101  FBMA-L11-453215-121LMA90T_2  [KC_FBMA-L11-453215-121LMA90T_2]  187.44 83.17 270 top
PL150  0.68UH_TMPC0624H-R68MG-D_13A_20%  [TAI-T_TMPC0624H-R68MG-D_2P]  147.47 78.35 180 bottom
PL200  1UH_NRS4018T1R0NDGJ_3.2A_30%  [TAIYO_NRS4018T1R0NDGJ_2P]  269.72 169.72 90 bottom
PL300  0.22UH_FDUE0640J-H-R2_25A_20%  [TOKO_FDUE0640J-H-R22M-P3_4P]  75.03 26.64 90 bottom
PL301  FBMA-L11-453215-121LMA90T_2  [KC_FBMA-L11-453215-121LMA90T_2]  61.44 29.32 270 bottom
PL400  1UH_PCMB053T-1R0MS_7A_20%  [CYNTE_PCMB053T-1R0MS_2P]  93.83 161.58 90 top
PL401  2.2UH_PCMB103T-2R2MS_13A_20%  [CYNTE_PCMB103T-2R2MS_2P]  102.52 161.73 0 bottom
PL601  0.22UH_FDUE0640J-H-R2_25A_20%  [TOKO_FDUE0640J-H-R22M-P3_4P]  71.54 50.28 90 bottom
PL602  0.22UH_FDUE0640J-H-R2_25A_20%  [TOKO_FDUE0640J-H-R22M-P3_4P]  54.06 52.95 58.3 bottom
PL700  1UH_FDSD0630-H-1R0M-P3_11A_20%  [TOKO_FDSD0630-H-1R0M-P3_2P]  44.61 41.22 90 bottom
PQ1  -  [DMG2301U-7_SOT23-3]  128.24 126.55 180 top
PQ2  -  [FDV301N-G_SOT23-3]  116.91 125.97 270 top
PQ3  -  [MMST3904-7-F_SOT323-3]  118.46 123.05 180 top
PQ4  -  [FDS6679AZ-G_SO8]  94.84 154.97 180 top
PQ5  -  [IMD2AGZT108_SC74-6]  121.38 125.53 270 top
PQ51  -  [SIS412DN-T1-GE3_POWERPAK8-5]  203.72 139.36 90 top
PQ52  -  [SIS412DN-T1-GE3_POWERPAK8-5]  203.72 143.02 90 top
PQ53  -  [SIS472DN-T1_POWERPAK1212-8-5]  200.85 137.66 270 top
PQ54  -  [SIS472DN-T1_POWERPAK1212-8-5]  200.85 148.68 270 top
PQ100  -  [SI4128DY-T1-GE3_SO8]  187.38 76.57 90 bottom
PQ101  -  [SI4134DY-T1-GE3_SO8]  179.89 76.57 90 bottom
PQ400  -  [AON7403L_DFN8-5]  98.75 151.92 180 top
PQ401  -  [NTR4502PT1G_SOT23-3]  106.52 134.01 0 top
PQ402  -  [NTR4502PT1G_SOT23-3]  110.59 134.01 0 top
PQ403  -  [SI3993CDV-T1-GE3_TSOP6]  113.6 135.94 270 top
PQ404  -  [SIR472DP-T1-GE3_POWERPAK8-5]  107.55 162.68 90 top
PQ406  -  [SIRA06DP-T1-GE_POWERPAKSO-8-5]  106.08 155.63 0 top
PQ409  -  [DMN66D0LDW-7_SOT363-6]  116.21 119.39 270 top
PQ410  -  [DMN65D8LW-7_SOT323-3]  113.19 117.34 0 top
PQ411  -  [DMN65D8LW-7_SOT323-3]  123.67 118.16 90 top
PQ500  -  [NTR4502PT1G_SOT23-3]  134.45 141.32 0 top
PQ501  -  [SI4835DDY-T1-GE3_SO8]  127 152.9 270 top
PQ502  -  [DMN66D0LDW-7_SOT363-6]  140.55 133.11 0 top
PQ503  -  [DMN66D0LDW-7_SOT363-6]  135.47 135.65 0 top
PQ504  -  [SI4835DDY-T1-GE3_SO8]  119.38 157.47 270 top
PQ505  -  [FDS6679AZ-G_SO8]  139.93 149.09 90 top
PQ506  -  [DMN66D0LDW-7_SOT363-6]  120.9 150.25 270 top
PQ507  -  [DMN66D0LDW-7_SOT363-6]  142.44 130.15 90 top
PQ508  -  [DMN65D8LW-7_SOT323-3]  140.81 124.32 270 top
PQ510  -  [FDS6679AZ-G_SO8]  140.06 159.38 90 top
PQ511  -  [FDS6679AZ-G_SO8]  132.46 164.74 180 top
PQ512  -  [DMN65D8LW-7_SOT323-3]  143.17 142.8 0 top
PQ514  -  [DMN65D8LW-7_SOT323-3]  142.85 149.34 0 top
PQ515  -  [DMN66D0LDW-7_SOT363-6]  130.9 124.14 0 top
PQ516  -  [DMN66D0LDW-7_SOT363-6]  141.08 142.97 180 top
PQ517  -  [NTR4502PT1G_SOT23-3]  130.28 132.47 180 top
PQ518  -  [DMG2301U-7_SOT23-3]  118.79 150.88 90 top
PQ519  -  [DMN66D0LDW-7_SOT363-6]  133.75 124.14 0 top
PQ520  -  [NTR4502PT1G_SOT23-3]  134.29 132.36 180 top
PQ521  -  [DMN65D8LW-7_SOT323-3]  141.01 138.99 0 top
PQ522  -  [NTR4502PT1G_SOT23-3]  128.59 143.91 0 top
PQ523  -  [DMN66D0LDW-7_SOT363-6]  130.58 139.53 0 top
PQ524  -  [FDMC6679AZ_MLP8-5]  134.02 166.89 270 top
PQ525  -  [AO3418_SOT23-3]  134.64 171.95 180 top
PQ526  -  [NTR4502PT1G_SOT23-3]  150.33 133.77 270 top
PQ527  -  [DMN65D8LW-7_SOT323-3]  150.49 130.46 270 top
PQ528  -  [DMN65D8LW-7_SOT323-3]  131.23 119.23 0 top
PQ529  -  [DMN65D8LW-7_SOT323-3]  112.24 155.84 0 top
PQ600  -  [SIR472DP-T1-GE3_POWERPAK8-5]  76.62 49.01 90 bottom
PQ601  -  [SIRA06DP-T1-GE_POWERPAKSO-8-5]  72.74 41.9 180 bottom
PQ602  -  [SIRA06DP-T1-GE_POWERPAKSO-8-5]  78.33 41.9 180 bottom
PQ603  -  [SIR472DP-T1-GE3_POWERPAK8-5]  61.5 51.24 90 bottom
PQ604  -  [SIRA06DP-T1-GE_POWERPAKSO-8-5]  60.61 43.87 180 bottom
PQ605  -  [SIRA06DP-T1-GE_POWERPAKSO-8-5]  54.9 43.87 180 bottom
PQ700  -  [SIS412DN-T1-GE3_POWERPAK8-5]  43.56 37.43 0 bottom
PQ701  -  [SI7716ADN-T1-GE3_POWERPAK8-5]  41.6 34.56 180 bottom
PR2  100K_0402_5%  [R_0402]  125.75 130.8 0 top
PR3  100_0402_5%  [R_0402]  99.47 168.14 0 top
PR4  100_0402_5%  [R_0402]  93.8 170.04 180 top
PR5  100_0402_5%  [R_0402]  99.47 170.04 0 top
PR8  2.2K_0402_5%  [R_0402]  124.13 124.07 180 top
PR9  33_0402_5%  [R_0402]  121.31 124.07 0 top
PR10  100K_0402_1%  [R_0402]  116.75 123.26 270 top
PR11  10K_0402_1%  [R_0402]  120.24 122.47 90 top
PR12  15K_0402_1%  [R_0402]  116.75 121.42 270 top
PR13  10K_0402_5%  [R_0402]  120.24 121.54 270 top
PR14  1M_0402_5%  [R_0402]  119.91 130.67 0 top
PR18  100K_0402_5%  [R_0402]  96.56 146.94 270 top
PR19  4.7K_0805_5%  [R_0805]  94.14 158.84 90 bottom
PR20  10K_0402_5%  [R_0402]  123.03 129.2 90 top
PR21  1M_0402_5%  [R_0402]  89.65 155.44 180 top
PR51  6.49K_0402_1%  [R_0402]  186.2 141.66 0 top
PR52  15.4K_0402_1%  [R_0402]  187.12 144.39 180 top
PR53  10K_0402_5%  [R_0402]  186.2 142.61 0 top
PR55  10K_0402_5%  [R_0402]  187.12 143.5 180 top
PR56  95.3K_0402_1%  [R_0402]  186.2 140.71 0 top
PR57  105K_0402_1%  [R_0402]  186.2 145.28 0 top
PR58  100K_0402_5%  [R_0402]  188.17 138.38 90 top
PR59  200_0402_1%  [R_0402]  189.2 146.35 90 top
PR60  0_0402_5%  [R0402_0OHM]  189.06 138.38 90 top
PR61  2.2_0603_5%  [R_0603]  191.61 146.8 90 top
PR62  2.2_0603_5%  [R_0603]  191.42 137.85 90 top
PR63  4.7_1206_5%  [R_1206]  198.98 134.55 90 top
PR64  4.7_1206_5%  [R_1206]  199.11 150.42 270 top
PR65  0_0402_5%  [R0402_0OHM]  187.35 148.07 0 top
PR100  2.2_0603_5%  [R_0603]  179.42 79.18 90 top
PR101  19.6K_0402_1%  [R_0402]  174.2 76.81 0 top
PR102  5.1_0603_5%  [R_0603]  175.23 77.96 180 top
PR103  4.7_1206_5%  [R_1206]  184.12 80.95 180 top
PR104  100K_0402_5%  [R_0402]  170.65 79.3 0 top
PR105  8.06K_0402_1%  [R_0402]  174.53 86.36 270 top
PR106  1M_0402_1%  [R_0402]  170.65 80.19 0 top
PR107  0_0402_5%  [R_0402]  170.65 81.08 0 top
PR108  0_0402_5%  [R0402_0OHM]  170.65 82.86 0 top
PR109  10K_0402_1%  [R_0402]  171.56 85.53 180 top
PR110  0_0402_5%  [R0402_0OHM]  170.65 83.75 0 top
PR111  0_0402_5%  [R_0402]  170.65 84.64 0 top
PR150  0_0402_5%  [R0402_0OHM]  155.74 79.12 270 bottom
PR153  0_0402_5%  [R_0402]  153.14 73.83 90 top
PR154  0_0402_5%  [R0402_0OHM]  152.25 73.83 90 top
PR155  4.7_1206_5%  [R_1206]  150.79 77.27 180 top
PR156  100K_0402_5%  [R_0402]  150.47 73.96 90 top
PR157  0_0402_5%  [R0402_0OHM]  149.2 74.93 270 top
PR158  5.1_0603_5%  [R_0603]  149.45 79.24 90 top
PR201  7.68K_0805_1%  [R_0805]  272.83 170.39 270 bottom
PR202  30.1K_0402_1%  [R_0402]  270.05 162.68 180 bottom
PR203  0_0402_5%  [R_0402]  272.08 166.49 180 bottom
PR204  20K_0402_1%  [R_0402]  268.21 163.57 180 bottom
PR205  1M_0402_5%  [R_0402]  271.17 165.6 0 bottom
PR206  0_0402_5%  [R0402_0OHM]  272.08 167.38 180 bottom
PR300  75_0402_1%  [R_0402]  46.02 23.36 180 bottom
PR301  348K_0402_1%  [R_0402]  50.06 14.09 0 bottom
PR302  75_0402_1%  [R_0402]  52.8 12.74 90 bottom
PR303  1M_0402_1%  [R_0402]  55.47 12.74 90 bottom
PR304  9.31K_0402_1%  [R_0402]  56.36 12.74 90 bottom
PR305  10K_0402_5%  [R_0402]  48.55 13.72 270 bottom
PR306  75K_0402_1%  [R_0402]  51.91 13.66 270 bottom
PR307  150K_0402_1%  [R_0402]  53.69 13.66 270 bottom
PR308  150K_0402_1%  [R_0402]  54.58 13.66 270 bottom
PR309  150K_0402_1%  [R_0402]  57.25 13.66 270 bottom
PR310  39K_0402_5%  [R_0402]  46.77 13.72 270 bottom
PR311  10K_0402_5%  [R_0402]  45.88 12.81 90 bottom
PR312  0_0402_5%  [R0402_0OHM]  54.95 15.04 0 bottom
PR313  0_0402_5%  [R_0402]  54.95 15.93 0 bottom
PR314  75_0402_1%  [R_0402]  57.12 16.55 90 bottom
PR315  0_0402_5%  [R0402_0OHM]  54.95 16.82 0 bottom
PR317  0_0402_5%  [R0402_0OHM]  54.95 18.6 0 bottom
PR318  0_0402_5%  [R_0402]  54.95 17.71 0 bottom
PR319  1.91K_0402_1%  [R_0402]  54.95 19.49 0 bottom
PR320  1_0603_5%  [R_0603]  55.09 20.56 0 bottom
PR321  0_0603_5%  [R_0603]  66.59 29.14 180 bottom
PR322  2.43K_0402_1%  [R_0402]  45.11 22.47 0 bottom
PR323  10K_0402_5%  [R_0402]  45.95 20.49 90 bottom
PR324  4.7_1206_5%  [R_1206]  72.43 19.61 90 bottom
PR325  5.62K_0402_1%  [R_0402]  45.9 19.55 180 bottom
PR326  0_0402_5%  [R0402_0OHM]  51.98 22.84 90 bottom
PR327  10_0603_1%  [R_0603]  48.36 23.93 270 bottom
PR328  2.1K_0402_1%  [R_0402]  70.66 30.53 180 bottom
PR329  3.01K_0402_1%  [R_0402]  70.65 32.33 270 bottom
PR330  130_0402_1%  [R_0402]  53.76 23.75 270 bottom
PR331  54.9_0402_1%  [R_0402]  52.87 23.75 270 bottom
PR333  49.9K_0402_1%  [R_0402]  69.76 32.33 270 bottom
PR334  0_0402_5%  [R0402_0OHM]  44.98 18.66 0 bottom
PR335  0_0402_5%  [R0402_0OHM]  44.98 17.77 0 bottom
PR400  0.01_1206_1%  [R_1206_4P-D]  98.59 153.19 90 top
PR402  0_0402_5%  [R0402_0OHM]  111.78 127.94 0 top
PR403  0_0402_5%  [R0402_0OHM]  112.57 138.36 180 top
PR404  150K_0402_1%  [R_0402]  112.7 128.83 180 top
PR405  100K_0402_1%  [R_0402]  111.78 129.72 0 top
PR408  44.2_0402_1%  [R_0402]  112.64 131.31 180 top
PR410  10K_0402_5%  [R_0402]  110.35 138.99 180 top
PR411  59_0402_1%  [R_0402]  112.64 132.26 180 top
PR417  100K_0402_5%  [R_0402]  115.24 138.67 180 top
PR418  100K_0402_5%  [R_0402]  115.24 137.79 180 top
PR420  10_1206_5%  [R_1206]  103.79 143.63 0 top
PR421  316K_0402_1%  [R_0402]  115.49 141.85 180 top
PR422  4.02K_0402_1%  [R_0402]  113.64 140.69 90 top
PR423  2.2_0603_5%  [R_0603]  107.35 146.68 180 top
PR424  49.9K_0402_1%  [R_0402]  115.49 143.63 180 top
PR425  100K_0402_1%  [R_0402]  107.3 149.34 180 top
PR426  0.01_1206_1%  [R_1206_4P-D]  116.94 163.34 270 top
PR427  0_0402_5%  [R0402_0OHM]  104.55 150.23 0 top
PR428  121K_0402_1%  [R_0402]  106.39 150.23 0 top
PR429  0_0402_5%  [R0402_0OHM]  115.49 145.47 180 top
PR430  0_0402_5%  [R0402_0OHM]  115.49 146.36 180 top
PR431  10K_0402_5%  [R_0402]  115.49 147.31 180 top
PR432  4.02K_0402_1%  [R_0402]  114.58 148.2 0 top
PR433  4.7_1206_5%  [R_1206]  103.8 159.88 270 top
PR435  221K_0402_1%  [R_0402]  114.15 118.53 90 top
PR437  1.8M_0402_1%  [R_0402]  114.01 125.4 0 top
PR440  150K_0402_1%  [R_0402]  114.92 120.83 180 top
PR441  20K_0402_1%  [R_0402]  114.92 126.36 180 top
PR442  0_0402_5%  [R0402_0OHM]  116.12 116.97 270 top
PR443  150K_0402_1%  [R_0402]  113.19 119.45 270 top
PR444  66.5K_0402_1%  [R_0402]  114.01 121.72 0 top
PR445  232K_0402_1%  [R_0402]  104.42 126.61 0 top
PR446  48.7K_0402_1%  [R_0402]  104.42 124.83 0 top
PR447  1M_0402_1%  [R_0402]  104.42 122.16 0 top
PR448  10K_0402_1%  [R_0402]  104.42 121.28 0 top
PR449  100K_0402_5%  [R_0402]  122.47 117.58 90 top
PR450  0_0402_5%  [R0402_0OHM]  105.33 120.39 180 top
PR451  22.6K_0402_1%  [R_0402]  106.32 126.61 0 top
PR452  42.2K_0402_1%  [R_0402]  105.33 123.94 180 top
PR453  10K_0402_1%  [R_0402]  106.2 120.15 0 top
PR500  100K_0402_5%  [R_0402]  143.99 131.77 270 top
PR501  240K_0402_5%  [R_0402]  135.36 139.45 270 top
PR502  100K_0402_5%  [R_0402]  125.13 150.56 270 top
PR503  100K_0402_5%  [R_0402]  133.44 139.44 0 top
PR504  100K_0402_5%  [R_0402]  139.16 135.07 270 top
PR505  100K_0402_5%  [R_0402]  138.15 137.48 270 top
PR506  100K_0402_5%  [R_0402]  142.08 123.87 90 top
PR507  10K_0402_5%  [R_0402]  124.18 149.65 90 top
PR508  100K_0402_5%  [R_0402]  118.88 148.42 0 top
PR509  330K_0402_5%  [R_0402]  133.91 147.82 270 top
PR510  820_0603_1%  [R_0603]  138.34 147.76 270 top
PR513  0_0402_5%  [R0402_0OHM]  144.75 161.48 270 top
PR514  0_0402_5%  [R0402_0OHM]  143.1 123.87 90 top
PR516  330K_0402_5%  [R_0402]  135.91 168.2 180 top
PR517  100K_0402_5%  [R_0402]  129.84 167.25 180 top
PR518  100K_0402_5%  [R_0402]  142.86 145.28 180 top
PR519  0_0402_5%  [R0402_0OHM]  147.8 153.61 270 top
PR520  10K_0402_5%  [R_0402]  129.5 168.2 0 top
PR521  100K_0402_5%  [R_0402]  142.85 151.45 270 top
PR522  100K_0402_5%  [R_0402]  141.95 146.23 0 top
PR523  0_0402_5%  [R0402_0OHM]  141.9 151.45 270 top
PR524  240K_0402_5%  [R_0402]  128.67 128.51 0 top
PR525  10K_0402_5%  [R_0402]  110.31 152.09 90 top
PR526  100K_0402_5%  [R_0402]  131.81 122.93 180 top
PR527  100K_0402_5%  [R_0402]  117.37 141.98 0 top
PR528  100K_0402_5%  [R_0402]  130.58 128.51 0 top
PR529  0_0402_5%  [R0402_0OHM]  117.37 138.42 0 top
PR530  0_0402_5%  [R_0402]  117.37 137.53 0 top
PR531  0_0402_5%  [R0402_0OHM]  118.29 139.31 180 top
PR532  100K_0402_5%  [R_0402]  139.16 138.47 90 top
PR533  47_0805_5%  [R_0805]  118.97 131.85 90 top
PR534  0_0402_5%  [R0402_0OHM]  118.29 141.09 180 top
PR535  240K_0402_5%  [R_0402]  132.86 128.51 0 top
PR536  0_0402_5%  [R0402_0OHM]  119.67 143.87 90 top
PR537  10K_0402_5%  [R_0402]  123.35 146.28 90 top
PR538  100K_0402_5%  [R_0402]  123.1 132.21 270 top
PR539  100K_0402_5%  [R_0402]  134.73 122.93 180 top
PR540  240K_0402_5%  [R_0402]  152.75 130.65 180 top
PR541  0_0402_5%  [R0402_0OHM]  122.15 131.3 90 top
PR542  0_0402_5%  [R0402_0OHM]  124.24 132.63 90 top
PR543  0_0402_5%  [R0402_0OHM]  120.56 143.87 90 top
PR544  100K_0402_5%  [R_0402]  134.77 128.51 0 top
PR545  0_0402_5%  [R0402_0OHM]  123.23 144 90 top
PR546  0_0402_5%  [R0402_0OHM]  124.11 144 90 top
PR547  1M_0402_5%  [R_0402]  124.24 146.28 90 top
PR548  0_0402_5%  [R0402_0OHM]  126.34 132.63 90 top
PR549  0_0402_5%  [R0402_0OHM]  125 144 90 top
PR550  0_0402_5%  [R0402_0OHM]  127.23 132.63 90 top
PR551  0_0402_5%  [R_0402]  125.89 144 90 top
PR552  0_0402_5%  [R0402_0OHM]  128.23 140.39 0 top
PR553  0_0402_5%  [R0402_0OHM]  128.23 141.28 0 top
PR554  240K_0402_5%  [R_0402]  131.54 145.74 270 top
PR555  47K_0402_5%  [R_0402]  131.54 143.83 270 top
PR556  1M_0402_5%  [R_0402]  128.23 139.5 0 top
PR557  100K_0402_5%  [R_0402]  130.4 137.2 90 top
PR558  0_0402_5%  [R0402_0OHM]  128.23 138.61 0 top
PR559  0_0402_5%  [R0402_0OHM]  118.29 140.2 180 top
PR560  0_0402_5%  [R0402_0OHM]  136.3 125.78 0 top
PR561  0_0402_5%  [R_0402]  134.86 127.05 180 top
PR562  0_0402_5%  [R0402_0OHM]  138.66 141.93 270 top
PR563  0_0402_5%  [R_0402]  131.53 127.05 0 top
PR564  0_0402_5%  [R0402_0OHM]  136.3 124.9 0 top
PR565  100K_0402_5%  [R_0402]  154.25 134.18 270 top
PR566  0_0402_5%  [R0402_0OHM]  129.39 119.02 270 top
PR567  0_0402_5%  [R0402_0OHM]  117.04 147.47 0 top
PR568  0_0402_5%  [R_0402]  117.02 148.41 0 top
PR600  0_0402_5%  [R_0402]  62.02 33.39 180 bottom
PR601  2.2_0603_1%  [R_0603]  60.04 39.74 90 bottom
PR602  0_0402_5%  [R_0402]  61.11 32.5 0 bottom
PR603  10K_0402_5%  [R_0402]  62.02 34.28 180 bottom
PR604  30K_0402_1%  [R_0402]  56.49 30.42 270 bottom
PR606  4.7_1206_5%  [R_1206]  80.24 47.49 270 bottom
PR607  3K_0402_1%  [R_0402]  58.26 28.62 90 bottom
PR608  39K_0402_1%  [R_0402]  57.37 30.47 0 bottom
PR610  24K_0402_1%  [R_0402]  57.33 25.71 180 bottom
PR611  3K_0402_1%  [R_0402]  56.41 26.66 0 bottom
PR614  510K_0402_1%  [R_0402]  54.71 29.51 90 bottom
PR615  0_0402_5%  [R0402_0OHM]  53.82 28.68 90 bottom
PR616  100_0402_5%  [R_0402]  52.93 28.68 90 bottom
PR617  2.2_0603_1%  [R_0603]  55.73 39.87 90 bottom
PR618  0_0402_5%  [R0402_0OHM]  50.26 27.22 90 bottom
PR619  0_0402_5%  [R_0402]  50.25 29.01 0 bottom
PR620  100_0402_5%  [R_0402]  51.15 27.22 90 bottom
PR621  0_0402_5%  [R_0402]  50.25 29.9 0 bottom
PR622  15.8K_0402_1%  [R_0402]  50.26 31.75 270 bottom
PR623  25.5K_0402_1%  [R_0402]  49.38 32.62 90 bottom
PR624  470K_0402_1%  [R_0402]  51.15 33.53 270 bottom
PR625  866_0402_1%  [R_0402]  50.26 33.53 270 bottom
PR626  10K_0402_5%  [R_0402]  51.2 38.15 0 bottom
PR627  0_0402_5%  [R0402_0OHM]  61.18 37.47 90 bottom
PR628  10K_0402_5%  [R_0402]  52.12 34.41 180 bottom
PR630  2.2_0603_1%  [R_0603]  49.85 37.62 180 bottom
PR631  2.2_0603_1%  [R_0603]  53.19 39.87 90 bottom
PR632  4.7_1206_5%  [R_1206]  49.25 48.82 270 bottom
PR633  0_0402_5%  [R_0402]  52.12 39.04 180 bottom
PR634  15.4K_0402_1%  [R_0402]  62.03 35.17 180 bottom
PR635  7.87K_0402_1%  [R_0402]  57.7 39.79 90 bottom
PR636  2.2_0402_1%  [R_0402]  49.83 36.57 180 bottom
PR637  0_0402_5%  [R_0402]  52.12 35.3 180 bottom
PR701  2.2_0603_5%  [R_0603]  37.06 28.44 0 bottom
PR702  40.2K_0402_1%  [R_0402]  31.9 29.33 0 bottom
PR703  0_0402_5%  [R_0402]  31.9 31.11 0 bottom
PR704  0_0402_5%  [R0402_0OHM]  31.9 30.22 0 bottom
PR705  470K_0402_1%  [R_0402]  34.24 33.27 0 bottom
PR706  4.7_1206_5%  [R_1206]  47.41 34.92 270 bottom
PR707  9.31K_0402_1%  [R_0402]  32.81 33.77 180 bottom
PR708  10K_0402_1%  [R_0402]  32.81 32.88 180 bottom
PR709  0_0402_5%  [R0402_0OHM]  34.9 28.44 180 bottom
PR710  0_0402_5%  [R0402_0OHM]  37.89 35.4 180 bottom
PR711  0_0402_5%  [R_0402]  37.89 34.33 180 bottom
